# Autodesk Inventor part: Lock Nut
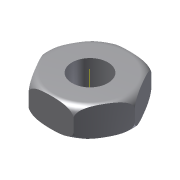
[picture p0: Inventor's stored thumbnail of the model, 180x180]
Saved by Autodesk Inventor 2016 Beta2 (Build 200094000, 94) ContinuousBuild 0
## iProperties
Created: 2009-04
Part Number: Lock Nut
Document SubType Name: Modeling
Designer: Sham
Density: 1 g/cm^3
Material: Generic
Appearance: Default
Author: Sham
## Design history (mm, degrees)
sketch "Sketch1"
  geometry: L1 (7.5, 12.99)-(15, 0); L2 (15, 0)-(7.5, -12.99); L3 (7.5, -12.99)-(-7.5, -12.99); L4 (-7.5, -12.99)-(-15, 0); L5 (-15, 0)-(-7.5, 12.99); L6 (-7.5, 12.99)-(7.5, 12.99); C1 r 6 at (0, 0); 1 further point
  constraints: 12 end point, 1 centre point, 1 coincident, 13 other
  dimensions: "d0" = 30 distance of L1.end L4.end; "d1" = 12 diameter of C1
extrude "Extrusion1" new body sketch "Sketch1" distance "d2" = 10; taper "d3" = 0 deg
sketch "Sketch2"
  geometry: L1 (-12, 0)-(-12, -0.022); L2 (-15, 7)-(-15, 3); L3 (0, -2.87)-(0, 12.87) reference; A1 r 3 centre (-12, 7) between (-12, 10) and (-15, 7); A2 r 3 centre (-12, 3) between (-15, 3) and (-12, 0)
  constraints: 4 end point, 4 point on circle, 2 centre point, 1 tangent
revolve "Revolution1" sketch "Sketch2" stored, may be unused: angle "d7" = 90 deg
body "Solid1"
other parameters: "d6" = 90 deg
